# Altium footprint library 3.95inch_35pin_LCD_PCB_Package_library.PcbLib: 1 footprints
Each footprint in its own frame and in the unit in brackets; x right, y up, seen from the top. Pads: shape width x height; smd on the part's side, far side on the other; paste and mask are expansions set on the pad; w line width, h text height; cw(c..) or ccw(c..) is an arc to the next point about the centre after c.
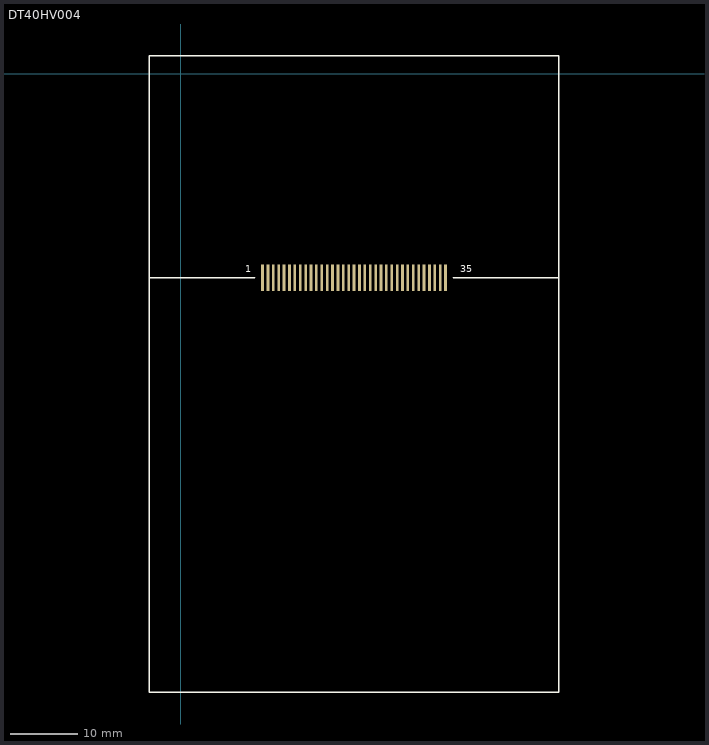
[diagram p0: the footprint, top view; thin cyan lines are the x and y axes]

## DT40HV004 [mm] "35pin LCD"
pads (35):
  rect 0.4x4 smd: 1(12.151,-30.313) 2(12.951,-30.313) 3(13.751,-30.313) 4(14.551,-30.313) 5(15.351,-30.313) 6(16.151,-30.313) 7(16.951,-30.313) 8(17.751,-30.313) 9(18.551,-30.313) 10(19.351,-30.313) 11(20.151,-30.313) 12(20.951,-30.313) 13(21.751,-30.313) 14(22.551,-30.313) 15(23.351,-30.313) 16(24.151,-30.313) 17(24.951,-30.313) 18(25.751,-30.313) 19(26.551,-30.313) 20(27.351,-30.313) 21(28.151,-30.313) 22(28.951,-30.313) 23(29.751,-30.313) 24(30.551,-30.313) 25(31.351,-30.313) 26(32.151,-30.313) 27(32.951,-30.313) 28(33.751,-30.313) 29(34.551,-30.313) 30(35.351,-30.313) 31(36.151,-30.313) 32(36.951,-30.313) 33(37.751,-30.313) 34(38.551,-30.313) 35(39.351,-30.313)
Top Overlay:
  lines w0.254: -4.699,-30.313 10.989,-30.313 ; 40.513,-30.313 56.141,-30.313 ; -4.699,-91.903 56.181,-91.903 56.181,2.667 -4.699,2.667 -4.699,-91.903
  text "35" at 41.549,-29.464 h1.02
  text "1" at 9.603,-29.464 h1.02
